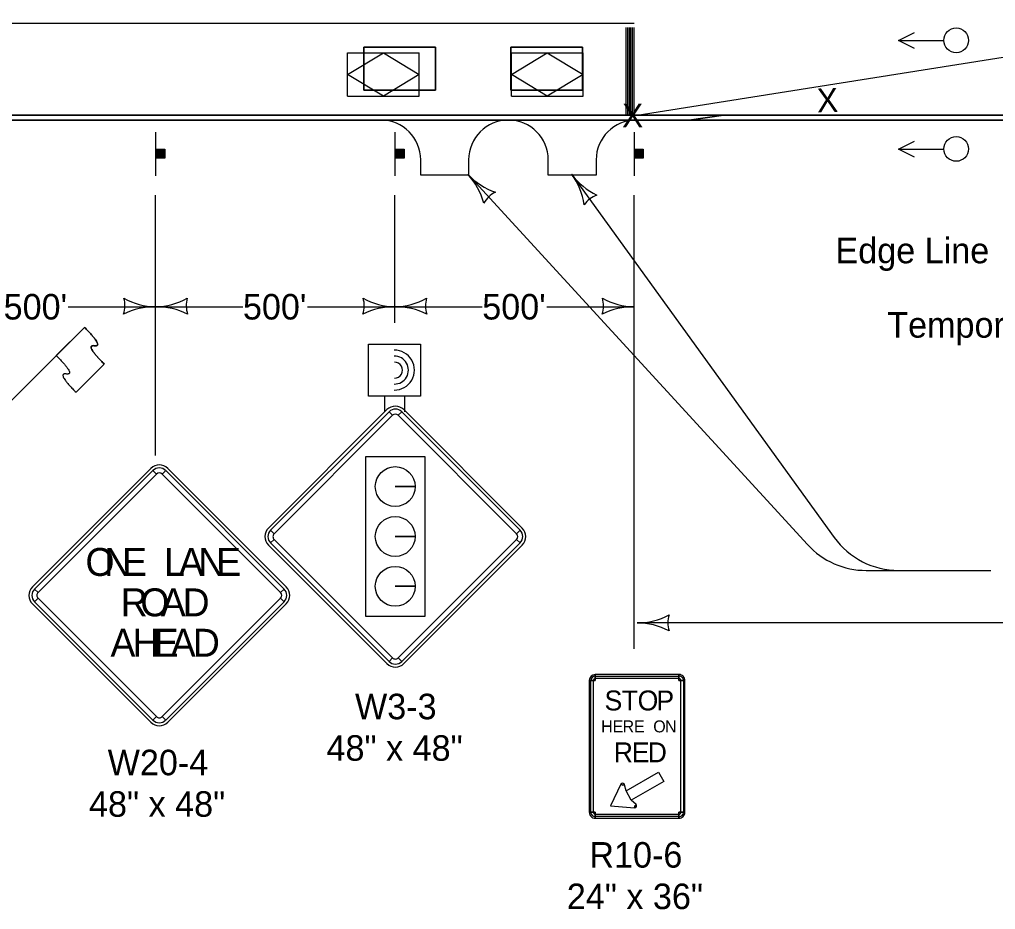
# Model space of a CAD drawing. Extents: x -2134934 to -2127057, y -2139046 to -2137036.
# Drawn here: x -2129917 to -2129305, y -2138163 to -2137605 of the extents above; entities that cross this region are included whole.
import ezdxf

# ---------------------------------------------------------------- set-up
doc = ezdxf.new("R2010")
doc.units = 0
for name, color, linetype in [('Barrier', 7, 'Continuous'), ('BridgeSuperStructureExisting', 7, 'Continuous'), ('DsnShtPlotIdentification', 7, 'Continuous'), ('DsnShtPlotShape', 7, 'Continuous'), ('dsnTextFinalPlan', 7, 'Continuous'), ('TC_Barrier', 7, 'Continuous')]:
    doc.layers.add(name, color=color, linetype=linetype)

msp = doc.modelspace()

# ---------------------------------------------------------------- linework, layer by layer
at = {"layer": 'Barrier'}
for p, q in [((-2129933.82, -2137855.42), (-2129876.5, -2137798.11)), ((-2129876.5, -2137798.11), (-2129894.18, -2137815.79)), ((-2129881.8, -2137838.78), (-2129864.12, -2137821.1)), ((-2129686.95, -2137849.65), (-2129761.19, -2137923.9)), ((-2129685.62, -2137850.98), (-2129683.41, -2137853.19)), ((-2129679.88, -2137853.19), (-2129677.67, -2137850.98)), ((-2129602.1, -2137923.9), (-2129676.34, -2137849.65)), ((-2129834.91, -2137886.48), (-2129909.16, -2137960.72)), ((-2129833.59, -2137887.8), (-2129831.38, -2137890.01)), ((-2129827.84, -2137890.01), (-2129825.63, -2137887.8)), ((-2129750.06, -2137960.72), (-2129824.31, -2137886.48)), ((-2129669.24, -2137897.87), (-2129681.74, -2137897.87)), ((-2129681.74, -2137897.87), (-2129669.24, -2137897.87)), ((-2129757.66, -2137927.43), (-2129759.87, -2137925.22)), ((-2129669.24, -2137929.12), (-2129681.74, -2137929.12)), ((-2129681.74, -2137929.12), (-2129669.24, -2137929.12)), ((-2129603.42, -2137925.22), (-2129605.63, -2137927.43)), ((-2129761.19, -2137934.5), (-2129686.95, -2138008.75)), ((-2129759.87, -2137933.18), (-2129757.66, -2137930.97)), ((-2129676.34, -2138008.75), (-2129602.1, -2137934.5)), ((-2129605.63, -2137930.97), (-2129603.42, -2137933.18)), ((-2129669.24, -2137960.37), (-2129681.74, -2137960.37)), ((-2129681.74, -2137960.37), (-2129669.24, -2137960.37)), ((-2129905.62, -2137964.26), (-2129907.83, -2137962.05)), ((-2129751.39, -2137962.05), (-2129753.59, -2137964.26)), ((-2129909.16, -2137971.33), (-2129834.91, -2138045.58)), ((-2129907.83, -2137970.01), (-2129905.62, -2137967.8)), ((-2129824.31, -2138045.58), (-2129750.06, -2137971.33)), ((-2129753.59, -2137967.8), (-2129751.39, -2137970.01)), ((-2129683.41, -2138005.21), (-2129685.62, -2138007.42)), ((-2129677.67, -2138007.42), (-2129679.88, -2138005.21)), ((-2129556.37, -2138019.4), (-2129556.37, -2138015.65)), ((-2129503.87, -2138015.65), (-2129503.87, -2138019.4)), ((-2129560.12, -2138019.4), (-2129556.37, -2138019.4)), ((-2129559.18, -2138019.4), (-2129557.62, -2138019.4)), ((-2129556.37, -2138018.15), (-2129556.37, -2138016.58)), ((-2129503.87, -2138016.58), (-2129503.87, -2138018.15)), ((-2129503.87, -2138019.4), (-2129500.12, -2138019.4)), ((-2129502.62, -2138019.4), (-2129501.05, -2138019.4)), ((-2129831.38, -2138042.04), (-2129833.59, -2138044.25)), ((-2129825.63, -2138044.25), (-2129827.84, -2138042.04)), ((-2129540.26, -2138084.38), (-2129539.15, -2138084.96)), ((-2129539.15, -2138084.96), (-2129537.93, -2138084.69)), ((-2129556.37, -2138101.9), (-2129560.12, -2138101.9)), ((-2129557.62, -2138101.9), (-2129559.18, -2138101.9)), ((-2129556.37, -2138105.65), (-2129556.37, -2138101.9)), ((-2129531.65, -2138097.95), (-2129531.7, -2138099.2)), ((-2129530.8, -2138097.03), (-2129531.65, -2138097.95)), ((-2129500.12, -2138101.9), (-2129503.87, -2138101.9)), ((-2129503.87, -2138101.9), (-2129503.87, -2138105.65)), ((-2129501.05, -2138101.9), (-2129502.62, -2138101.9)), ((-2129556.37, -2138104.71), (-2129556.37, -2138103.15)), ((-2129503.87, -2138103.15), (-2129503.87, -2138104.71))]:
    msp.add_line(p, q, dxfattribs=at)
for points in [[(-2129685.62, -2137850.98), (-2129759.87, -2137925.22), (-2129757.66, -2137927.43), (-2129683.41, -2137853.19), (-2129685.62, -2137850.98)], [(-2129603.42, -2137925.22), (-2129677.67, -2137850.98), (-2129679.88, -2137853.19), (-2129605.63, -2137927.43), (-2129603.42, -2137925.22)], [(-2129662.91, -2137879.26), (-2129700.38, -2137879.26), (-2129700.38, -2137979.15), (-2129662.91, -2137979.15), (-2129662.91, -2137879.26)], [(-2129833.59, -2137887.8), (-2129907.83, -2137962.05), (-2129905.62, -2137964.26), (-2129831.38, -2137890.01), (-2129833.59, -2137887.8)], [(-2129751.39, -2137962.05), (-2129825.63, -2137887.8), (-2129827.84, -2137890.01), (-2129753.59, -2137964.26), (-2129751.39, -2137962.05)], [(-2129759.87, -2137933.18), (-2129685.62, -2138007.42), (-2129683.41, -2138005.21), (-2129757.66, -2137930.97), (-2129759.87, -2137933.18)], [(-2129677.67, -2138007.42), (-2129603.42, -2137933.18), (-2129605.63, -2137930.97), (-2129679.88, -2138005.21), (-2129677.67, -2138007.42)], [(-2129907.83, -2137970.01), (-2129833.59, -2138044.25), (-2129831.38, -2138042.04), (-2129905.62, -2137967.8), (-2129907.83, -2137970.01)], [(-2129825.63, -2138044.25), (-2129751.39, -2137970.01), (-2129753.59, -2137967.8), (-2129827.84, -2138042.04), (-2129825.63, -2138044.25)], [(-2129556.37, -2138105.65), (-2129503.87, -2138105.65), (-2129503.87, -2138101.9), (-2129500.12, -2138101.9), (-2129500.12, -2138019.4), (-2129503.87, -2138019.4), (-2129503.87, -2138015.65), (-2129556.37, -2138015.65), (-2129556.37, -2138019.4), (-2129560.12, -2138019.4), (-2129560.12, -2138101.9), (-2129556.37, -2138101.9), (-2129556.37, -2138105.65)], [(-2129557.62, -2138019.4), (-2129557.62, -2138101.9), (-2129559.18, -2138101.9), (-2129559.18, -2138019.4), (-2129557.62, -2138019.4)], [(-2129503.87, -2138018.15), (-2129556.37, -2138018.15), (-2129556.37, -2138016.58), (-2129503.87, -2138016.58), (-2129503.87, -2138018.15)], [(-2129502.62, -2138101.9), (-2129502.62, -2138019.4), (-2129501.05, -2138019.4), (-2129501.05, -2138101.9), (-2129502.62, -2138101.9)], [(-2129516.74, -2138076.9), (-2129513.46, -2138082.58), (-2129533.77, -2138094.3), (-2129537.05, -2138088.62), (-2129516.74, -2138076.9)], [(-2129546.77, -2138098.02), (-2129531.7, -2138099.2), (-2129531.65, -2138097.95), (-2129530.8, -2138097.03), (-2129533.77, -2138094.3), (-2129537.05, -2138088.62), (-2129537.93, -2138084.69), (-2129539.15, -2138084.96), (-2129540.26, -2138084.38), (-2129546.77, -2138098.02)], [(-2129556.37, -2138103.15), (-2129503.87, -2138103.15), (-2129503.87, -2138104.71), (-2129556.37, -2138104.71), (-2129556.37, -2138103.15)]]:
    msp.add_lwpolyline(points, close=True, dxfattribs=at)
for centre in [(-2129681.74, -2137897.87), (-2129681.74, -2137929.12), (-2129681.74, -2137960.37)]:
    msp.add_circle(centre, 12.5, dxfattribs=at)
for centre, radius, start, end in [((-2129681.64, -2137854.96), 7.5, 44.99999, 134.99974), ((-2129681.64, -2137854.96), 5.62, 44.99999, 134.99974), ((-2129681.64, -2137854.96), 2.5, 44.99999, 134.99974), ((-2129829.61, -2137891.78), 7.5, 44.99999, 134.99974), ((-2129829.61, -2137891.78), 5.62, 44.99999, 134.99974), ((-2129829.61, -2137891.78), 2.5, 44.99999, 134.99974), ((-2129755.89, -2137929.2), 7.5, 134.99974, 224.99995), ((-2129607.4, -2137929.2), 7.5, 315.00016, 44.9998), ((-2129755.89, -2137929.2), 5.62, 134.99974, 224.99995), ((-2129755.89, -2137929.2), 2.5, 134.99974, 224.99995), ((-2129607.4, -2137929.2), 2.5, 315.00016, 44.9998), ((-2129607.4, -2137929.2), 5.62, 315.00016, 44.9998), ((-2129903.85, -2137966.03), 7.5, 134.99974, 224.99995), ((-2129755.36, -2137966.03), 7.5, 315.00016, 44.9998), ((-2129903.85, -2137966.03), 5.62, 134.99974, 224.99995), ((-2129903.85, -2137966.03), 2.5, 134.99974, 224.99995), ((-2129755.36, -2137966.03), 2.5, 315.00016, 44.9998), ((-2129755.36, -2137966.03), 5.62, 315.00016, 44.9998), ((-2129681.64, -2138003.45), 7.5, 224.99995, 315.00016), ((-2129681.64, -2138003.45), 5.62, 224.99995, 315.00016), ((-2129681.64, -2138003.45), 2.5, 224.99995, 315.00016), ((-2129556.37, -2138019.4), 3.75, 90.00021, 179.99985), ((-2129503.87, -2138019.4), 3.75, 0, 90.00021), ((-2129556.37, -2138019.4), 2.81, 90.00021, 179.99985), ((-2129556.37, -2138019.4), 1.25, 90.00021, 179.99985), ((-2129503.87, -2138019.4), 2.81, 0, 90.00021), ((-2129503.87, -2138019.4), 1.25, 0, 90.00021), ((-2129829.61, -2138040.27), 7.5, 224.99995, 315.00016), ((-2129829.61, -2138040.27), 5.62, 224.99995, 315.00016), ((-2129829.61, -2138040.27), 2.5, 224.99995, 315.00016), ((-2129539.15, -2138084.96), 1.25, 12.62232, 152.27557), ((-2129556.37, -2138101.9), 3.75, 179.99985, 270.00006), ((-2129556.37, -2138101.9), 2.81, 179.99985, 270.00006), ((-2129556.37, -2138101.9), 1.25, 179.99985, 270.00006), ((-2129531.65, -2138097.95), 1.25, 267.72427, 47.37758), ((-2129503.87, -2138101.9), 3.75, 270.00006, 0.00027), ((-2129503.87, -2138101.9), 2.81, 270.00006, 0.00027), ((-2129503.87, -2138101.9), 1.25, 270.00006, 0.00027)]:
    msp.add_arc(centre, radius, start, end, dxfattribs=at)
for points in [[(-2129864.12, -2137821.1), (-2129876.5, -2137808.72), (-2129864.12, -2137810.49), (-2129876.5, -2137798.11)], [(-2129894.18, -2137815.79), (-2129881.8, -2137828.17), (-2129894.17, -2137826.4), (-2129881.8, -2137838.78)]]:
    msp.add_open_spline(points, degree=2, dxfattribs=at)
at = {"layer": 'BridgeSuperStructureExisting'}
for p, q in [((-2129530.12, -2137665.16), (-2129152.26, -2137605.17)), ((-2129536.95, -2137665.16), (-2129536.95, -2137610.16)), ((-2129535.95, -2137665.16), (-2129535.95, -2137610.16)), ((-2129534.95, -2137665.16), (-2129534.95, -2137610.16)), ((-2129533.95, -2137665.16), (-2129533.95, -2137610.16)), ((-2129532.95, -2137665.16), (-2129532.95, -2137610.16)), ((-2129531.95, -2137665.16), (-2129531.95, -2137610.16)), ((-2129337.85, -2137618.58), (-2129365.8, -2137618.58)), ((-2129701.47, -2137622.46), (-2129656.47, -2137622.46)), ((-2129701.47, -2137649.46), (-2129701.47, -2137622.46)), ((-2129656.47, -2137622.46), (-2129701.47, -2137622.46)), ((-2129701.47, -2137622.46), (-2129701.47, -2137649.46)), ((-2129656.47, -2137622.46), (-2129656.47, -2137649.46)), ((-2129656.47, -2137649.46), (-2129656.47, -2137622.46)), ((-2129609.28, -2137622.54), (-2129564.28, -2137622.54)), ((-2129609.28, -2137649.54), (-2129609.28, -2137622.54)), ((-2129564.28, -2137622.54), (-2129609.28, -2137622.54)), ((-2129609.28, -2137622.54), (-2129609.28, -2137649.54)), ((-2129564.28, -2137622.54), (-2129564.28, -2137649.54)), ((-2129564.28, -2137649.54), (-2129564.28, -2137622.54)), ((-2129711.63, -2137653.13), (-2129711.63, -2137626.13)), ((-2129711.63, -2137626.13), (-2129666.63, -2137626.13)), ((-2129666.63, -2137653.13), (-2129666.63, -2137626.13)), ((-2129608.95, -2137653.13), (-2129608.95, -2137626.13)), ((-2129608.95, -2137626.13), (-2129563.95, -2137626.13)), ((-2129563.95, -2137653.13), (-2129563.95, -2137626.13)), ((-2129656.47, -2137649.46), (-2129701.47, -2137649.46)), ((-2129701.47, -2137649.46), (-2129656.47, -2137649.46)), ((-2129711.63, -2137653.13), (-2129666.63, -2137653.13)), ((-2129564.28, -2137649.54), (-2129609.28, -2137649.54)), ((-2129609.28, -2137649.54), (-2129564.28, -2137649.54)), ((-2129608.95, -2137653.13), (-2129563.95, -2137653.13)), ((-2130182.57, -2137665.16), (-2128870.12, -2137665.16)), ((-2129690.77, -2137668.16), (-2129610.77, -2137668.16)), ((-2129639.46, -2137668.16), (-2129614.46, -2137668.16)), ((-2129610.77, -2137668.16), (-2129530.77, -2137668.16)), ((-2129831.95, -2137675.66), (-2129831.95, -2137703.16)), ((-2129681.95, -2137675.66), (-2129681.95, -2137703.16)), ((-2129531.95, -2137675.66), (-2129531.95, -2137703.16)), ((-2129831.54, -2137692.11), (-2129831.54, -2137686.52)), ((-2129831.26, -2137686.52), (-2129831.26, -2137692.11)), ((-2129830.99, -2137692.11), (-2129830.99, -2137686.52)), ((-2129830.73, -2137686.52), (-2129830.73, -2137692.11)), ((-2129830.51, -2137692.11), (-2129830.51, -2137686.52)), ((-2129830.3, -2137686.52), (-2129830.3, -2137692.11)), ((-2129829.96, -2137692.11), (-2129829.96, -2137686.52)), ((-2129829.7, -2137686.52), (-2129829.7, -2137692.11)), ((-2129829.47, -2137692.11), (-2129829.49, -2137686.52)), ((-2129829.16, -2137686.52), (-2129829.16, -2137692.11)), ((-2129828.78, -2137692.11), (-2129828.78, -2137686.52)), ((-2129828.35, -2137686.52), (-2129828.35, -2137692.11)), ((-2129828.12, -2137692.11), (-2129828.14, -2137686.52)), ((-2129827.71, -2137686.52), (-2129827.69, -2137692.11)), ((-2129827.49, -2137692.11), (-2129827.49, -2137686.52)), ((-2129827.17, -2137686.52), (-2129827.17, -2137692.11)), ((-2129826.94, -2137692.11), (-2129826.94, -2137686.52)), ((-2129826.62, -2137686.52), (-2129826.62, -2137692.11)), ((-2129681.54, -2137692.11), (-2129681.54, -2137686.52)), ((-2129681.26, -2137686.52), (-2129681.26, -2137692.11)), ((-2129680.99, -2137692.11), (-2129680.99, -2137686.52)), ((-2129680.73, -2137686.52), (-2129680.73, -2137692.11)), ((-2129680.51, -2137692.11), (-2129680.51, -2137686.52)), ((-2129680.3, -2137686.52), (-2129680.3, -2137692.11)), ((-2129679.96, -2137692.11), (-2129679.96, -2137686.52)), ((-2129679.7, -2137686.52), (-2129679.7, -2137692.11)), ((-2129679.48, -2137692.11), (-2129679.49, -2137686.52)), ((-2129679.16, -2137686.52), (-2129679.16, -2137692.11)), ((-2129678.78, -2137692.11), (-2129678.78, -2137686.52)), ((-2129678.35, -2137686.52), (-2129678.35, -2137692.11)), ((-2129678.13, -2137692.11), (-2129678.14, -2137686.52)), ((-2129677.71, -2137686.52), (-2129677.69, -2137692.11)), ((-2129677.49, -2137692.11), (-2129677.49, -2137686.52)), ((-2129677.17, -2137686.52), (-2129677.17, -2137692.11)), ((-2129676.94, -2137692.11), (-2129676.94, -2137686.52)), ((-2129676.63, -2137686.52), (-2129676.63, -2137692.11)), ((-2129531.54, -2137692.11), (-2129531.54, -2137686.52)), ((-2129531.26, -2137686.52), (-2129531.26, -2137692.11)), ((-2129530.99, -2137692.11), (-2129530.99, -2137686.52)), ((-2129530.73, -2137686.52), (-2129530.73, -2137692.11)), ((-2129530.51, -2137692.11), (-2129530.51, -2137686.52)), ((-2129530.3, -2137686.52), (-2129530.3, -2137692.11)), ((-2129529.96, -2137692.11), (-2129529.96, -2137686.52)), ((-2129529.7, -2137686.52), (-2129529.7, -2137692.11)), ((-2129529.48, -2137692.11), (-2129529.49, -2137686.52)), ((-2129529.16, -2137686.52), (-2129529.16, -2137692.11)), ((-2129528.78, -2137692.11), (-2129528.78, -2137686.52)), ((-2129528.35, -2137686.52), (-2129528.35, -2137692.11)), ((-2129528.13, -2137692.11), (-2129528.14, -2137686.52)), ((-2129527.71, -2137686.52), (-2129527.69, -2137692.11)), ((-2129527.49, -2137692.11), (-2129527.49, -2137686.52)), ((-2129527.17, -2137686.52), (-2129527.17, -2137692.11)), ((-2129526.94, -2137692.11), (-2129526.94, -2137686.52)), ((-2129526.63, -2137686.52), (-2129526.63, -2137692.11)), ((-2129337.85, -2137686.64), (-2129365.8, -2137686.64)), ((-2129636.21, -2137702.17), (-2129423.31, -2137934.21)), ((-2129571.15, -2137702.12), (-2129406.64, -2137929.7)), ((-2129831.95, -2137878.33), (-2129831.95, -2137715.16)), ((-2129681.95, -2137795.16), (-2129681.95, -2137715.16)), ((-2129531.95, -2137999.46), (-2129531.95, -2137715.16)), ((-2129886.7, -2137785.16), (-2129831.95, -2137785.16)), ((-2129831.95, -2137785.16), (-2129777.2, -2137785.16)), ((-2129736.7, -2137785.16), (-2129681.95, -2137785.16)), ((-2129681.95, -2137785.16), (-2129627.2, -2137785.16)), ((-2129586.7, -2137785.16), (-2129531.95, -2137785.16)), ((-2129688.49, -2137841.1), (-2129688.49, -2137851.1)), ((-2129675.99, -2137841.1), (-2129675.99, -2137851.1)), ((-2129386.47, -2137950.41), (-2129308.33, -2137950.41)), ((-2128866.54, -2137983.33), (-2129530.12, -2137983.33))]:
    msp.add_line(p, q, dxfattribs=at)
for points in [[(-2129356.17, -2137623.39), (-2129366.17, -2137618.39), (-2129356.17, -2137613.39)], [(-2129356.17, -2137691.45), (-2129366.17, -2137686.45), (-2129356.17, -2137681.45)], [(-2129635.77, -2137693.16), (-2129635.77, -2137702.65), (-2129665.77, -2137702.65), (-2129665.77, -2137693.16)], [(-2129555.77, -2137693.16), (-2129555.77, -2137702.65), (-2129585.77, -2137702.65), (-2129585.77, -2137693.16)]]:
    msp.add_lwpolyline(points, dxfattribs=at)
for points in [[(-2129831.86, -2137692.11), (-2129831.86, -2137686.48), (-2129826.23, -2137686.48), (-2129826.23, -2137692.11)], [(-2129681.86, -2137692.11), (-2129681.86, -2137686.48), (-2129676.23, -2137686.48), (-2129676.23, -2137692.11)], [(-2129531.86, -2137692.11), (-2129531.86, -2137686.48), (-2129526.23, -2137686.48), (-2129526.23, -2137692.11)], [(-2129698.49, -2137841.1), (-2129698.49, -2137808.6), (-2129665.99, -2137808.6), (-2129665.99, -2137841.1)]]:
    msp.add_lwpolyline(points, close=True, dxfattribs=at)
for centre in [(-2129330.12, -2137618.21), (-2129330.12, -2137686.27)]:
    msp.add_circle(centre, 7.74, dxfattribs=at)
for centre, radius, start, end in [((-2129690.77, -2137693.16), 25, 0, 90), ((-2129610.77, -2137693.16), 25, 90, 180), ((-2129610.77, -2137693.16), 25, 0, 90), ((-2129530.77, -2137693.16), 25, 90, 180), ((-2129867.57, -2137784.54), 16.42, 341.26665, 16.73335), ((-2129831.2, -2137742.67), 42.5, 240.92751, 268.9824), ((-2129832.71, -2137742.67), 42.5, 271.0176, 299.07249), ((-2129796.33, -2137784.54), 16.42, 163.26665, 198.73335), ((-2129717.57, -2137784.54), 16.42, 341.26665, 16.73335), ((-2129681.2, -2137742.67), 42.5, 240.92751, 268.9824), ((-2129682.71, -2137742.67), 42.5, 271.0176, 299.07249), ((-2129646.33, -2137784.54), 16.42, 163.26665, 198.73335), ((-2129567.57, -2137784.54), 16.42, 341.26665, 16.73335), ((-2129531.2, -2137742.67), 42.5, 240.92751, 268.9824), ((-2129832.68, -2137827.65), 42.5, 89.0176, 117.07249), ((-2129831.22, -2137827.65), 42.5, 62.92751, 90.9824), ((-2129682.68, -2137827.65), 42.5, 89.0176, 117.07249), ((-2129681.22, -2137827.65), 42.5, 62.92751, 90.9824), ((-2129532.68, -2137827.65), 42.5, 89.0176, 117.07249), ((-2129682.23, -2137824.87), 12.5, 269.40414, 90.54446), ((-2129682.23, -2137824.87), 12.5, 269.40414, 90.54446), ((-2129682.23, -2137824.87), 8.75, 269.40414, 90.54446), ((-2129682.23, -2137824.87), 5, 269.40414, 90.54446), ((-2129366.12, -2137900.41), 50, 215.86205, 270), ((-2129386.47, -2137900.41), 50, 222.53616, 270)]:
    msp.add_arc(centre, radius, start, end, dxfattribs=at)
at = {"layer": 'DsnShtPlotIdentification'}
for p, q in [((-2129531.95, -2137607.66), (-2130184.45, -2137607.66)), ((-2129535.12, -2137665.16), (-2130182.57, -2137665.16)), ((-2130181.95, -2137665.16), (-2128681.95, -2137665.16)), ((-2129475.87, -2137665.16), (-2129530.12, -2137665.16)), ((-2129497.55, -2137668.16), (-2129475.87, -2137665.16)), ((-2129475.87, -2137665.16), (-2129497.55, -2137668.16)), ((-2129182.92, -2137665.16), (-2129475.87, -2137665.16)), ((-2130182.57, -2137668.16), (-2129497.55, -2137668.16)), ((-2129497.55, -2137668.16), (-2129183.89, -2137668.16))]:
    msp.add_line(p, q, dxfattribs=at)
for points in [[(-2128870.12, -2137665.16), (-2130182.57, -2137665.16)], [(-2129532.12, -2137665.16), (-2129533.12, -2137665.16), (-2129534.12, -2137665.16), (-2129535.12, -2137665.16)], [(-2129530.12, -2137665.16), (-2129531.12, -2137665.16), (-2129532.12, -2137665.16)], [(-2128870.12, -2137668.16), (-2130182.57, -2137668.16)]]:
    msp.add_lwpolyline(points, dxfattribs=at)
at = {"layer": 'DsnShtPlotShape'}
for centre, radius, start, end in [((-2129605.11, -2137673.2), 42.5, 222.97313, 251.04562), ((-2129667.3, -2137731.14), 42.5, 14.90064, 42.97313), ((-2129536.9, -2137676.96), 42.5, 216.29902, 244.37151), ((-2129605.4, -2137727.28), 42.5, 8.22653, 36.29902), ((-2129611.91, -2137728.24), 16.42, 115.23978, 150.70648), ((-2129550.05, -2137730.84), 16.42, 108.56567, 144.03237), ((-2129530.12, -2137940.83), 42.5, 270, 298.07249), ((-2129494.48, -2137983.33), 16.42, 162.26665, 197.73335), ((-2129530.12, -2138025.83), 42.5, 61.92751, 90)]:
    msp.add_arc(centre, radius, start, end, dxfattribs=at)
at = {"layer": 'dsnTextFinalPlan'}
for points in [[(-2129711.63, -2137639.63), (-2129689.13, -2137626.13), (-2129666.63, -2137639.63), (-2129689.13, -2137653.13)], [(-2129608.95, -2137639.63), (-2129586.45, -2137626.13), (-2129563.95, -2137639.63), (-2129586.45, -2137653.13)]]:
    msp.add_lwpolyline(points, close=True, dxfattribs=at)
at = {"layer": 'TC_Barrier'}
msp.add_line((-2129864.12, -2137821.1), (-2129881.8, -2137838.78), dxfattribs=at)
for points in [[(-2129876.5, -2137798.11), (-2129864.12, -2137810.49), (-2129876.5, -2137808.72), (-2129864.12, -2137821.1)], [(-2129894.18, -2137815.79), (-2129881.8, -2137828.17), (-2129894.17, -2137826.4), (-2129881.8, -2137838.78)]]:
    msp.add_open_spline(points, degree=2, dxfattribs=at)

# ---------------------------------------------------------------- texts
at = {"layer": 'Barrier'}
for s, height, p in [('O', 17.5, (-2129875.89, -2137953.84)), ('N', 17.5, (-2129864.12, -2137953.84)), ('E', 17.5, (-2129852.89, -2137953.84)), ('L', 17.5, (-2129826.64, -2137953.84)), ('A', 17.5, (-2129817.44, -2137953.84)), ('N', 17.5, (-2129805.18, -2137953.84)), ('E', 17.5, (-2129793.95, -2137953.84)), ('O', 17.5, (-2129841.5, -2137979.15)), ('R', 17.5, (-2129853.79, -2137979.15)), ('A', 17.5, (-2129828.66, -2137979.15)), ('D', 17.5, (-2129815, -2137979.15)), ('A', 17.5, (-2129860.22, -2138004.47)), ('H', 17.5, (-2129846.36, -2138004.47)), ('E', 17.5, (-2129833.14, -2138004.47)), ('A', 17.5, (-2129822.43, -2138004.47)), ('D', 17.5, (-2129808.56, -2138004.47)), ('W3-3', 16, (-2129706.94, -2138043.67)), ('S', 12.5, (-2129550.56, -2138038.15)), ('T', 12.5, (-2129539.8, -2138038.15)), ('O', 12.5, (-2129529.81, -2138038.15)), ('P', 12.5, (-2129518.07, -2138038.15)), ('H', 7.5, (-2129552.64, -2138051.9)), ('E', 7.5, (-2129545.49, -2138051.9)), ('R', 7.5, (-2129539.23, -2138051.9)), ('E', 7.5, (-2129532.08, -2138051.9)), ('O', 7.5, (-2129520.01, -2138051.9)), ('N', 7.5, (-2129512.63, -2138051.9)), ('48" x 48"', 16, (-2129724.81, -2138069.67)), ('R', 12.5, (-2129544.8, -2138070.65)), ('E', 12.5, (-2129533.47, -2138070.65)), ('D', 12.5, (-2129523.51, -2138070.65)), ('W20-4', 16, (-2129861.97, -2138078.77)), ('48" x 48"', 16, (-2129873.68, -2138104.77)), ('R10-6', 16, (-2129560.04, -2138136.65)), ('24" x 36"', 16, (-2129574.18, -2138162.65))]:
    msp.add_text(s, height=height, dxfattribs=at).set_placement(p)
at = {"layer": 'BridgeSuperStructureExisting'}
msp.add_text('X', height=15, rotation=2.01097, dxfattribs=at).set_placement((-2129417.23, -2137663.45))
for s, height, p in [('X', 15, (-2129539.63, -2137672.81)), ('Edge Line', 16, (-2129405.77, -2137757.93)), ("500'", 16, (-2129927.2, -2137793.16)), ("500'", 16, (-2129777.2, -2137793.16)), ("500'", 16, (-2129627.2, -2137793.16)), ('Temporary Crash Cushion', 16, (-2129373.33, -2137804.53))]:
    msp.add_text(s, height=height, dxfattribs=at).set_placement(p)

doc.saveas('drawing.dxf')
